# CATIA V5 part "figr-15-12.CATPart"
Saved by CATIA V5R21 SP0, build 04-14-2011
Part number: Part1
Bounding box of the stored display mesh (mm): x -50 to 50, y -32.5 to 33.5, z -52 to 1
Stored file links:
  D:\CATIA V5R21 E-RESOURCES\CATIA-V5R21\catia-v5r21-Prts\c15_catia_v5r21_prt\figr-15-12.CATPart
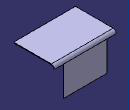
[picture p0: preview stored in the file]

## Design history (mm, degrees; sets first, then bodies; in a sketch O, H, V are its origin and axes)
SheetMetalParameters1: Thickness 1, BendRadius 4, KFactor 0.475772 {= log(min(100,max(20*SheetMetalParameters1.BendRadius,SheetMetalParameters1.Thickness)/SheetMetalParameters1.Thickness))/log(100)/2}, ReliefRadialLength 4, ReliefAxialLength 4, MinimumBendRadius 0
Body1 (main body)
  Sketch1 on xy-plane, origin (0, 0, 0), H (1, 0, 0), V (0, 1, 0)
    line L1 (-50, 32.5) -> (50, 32.5)
    line L2 (50, 32.5) -> (50, -32.5)
    line L3 (50, -32.5) -> (-50, -32.5)
    line L4 (-50, -32.5) -> (-50, 32.5)
    length L1 = 100
    length L2 = 65
    horizontal: L1 H, L3 H
    vertical: L2 V, L4 V
    symmetry: L4 L2 V, L1 L3 H
  Wall1: Thickness 1, Profile Sketch1
  d_NewWallOnEdge1: NewWallOnEdge_Edge edge [face of Wall1 | face of Wall1], NewWallOnEdge_Length 53, NewWallOnEdge_HeightLimitOffset 0, NewWallOnEdge_WidthOffset1 -15, NewWallOnEdge_WidthOffset2 -15, NewWallOnEdge_Angle 90, NewWallOnEdge_BendRadiusValue 4 {= SheetMetalParameters1.BendRadius}, NewWallOnEdge_BendTable SheetMetalParameters1, KFacteur 0.475772 {= log(min(100,max(20*d_NewWallOnEdge1.Radius,SheetMetalParameters1.Thickness)/SheetMetalParameters1.Thickness))/log(100)/2}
